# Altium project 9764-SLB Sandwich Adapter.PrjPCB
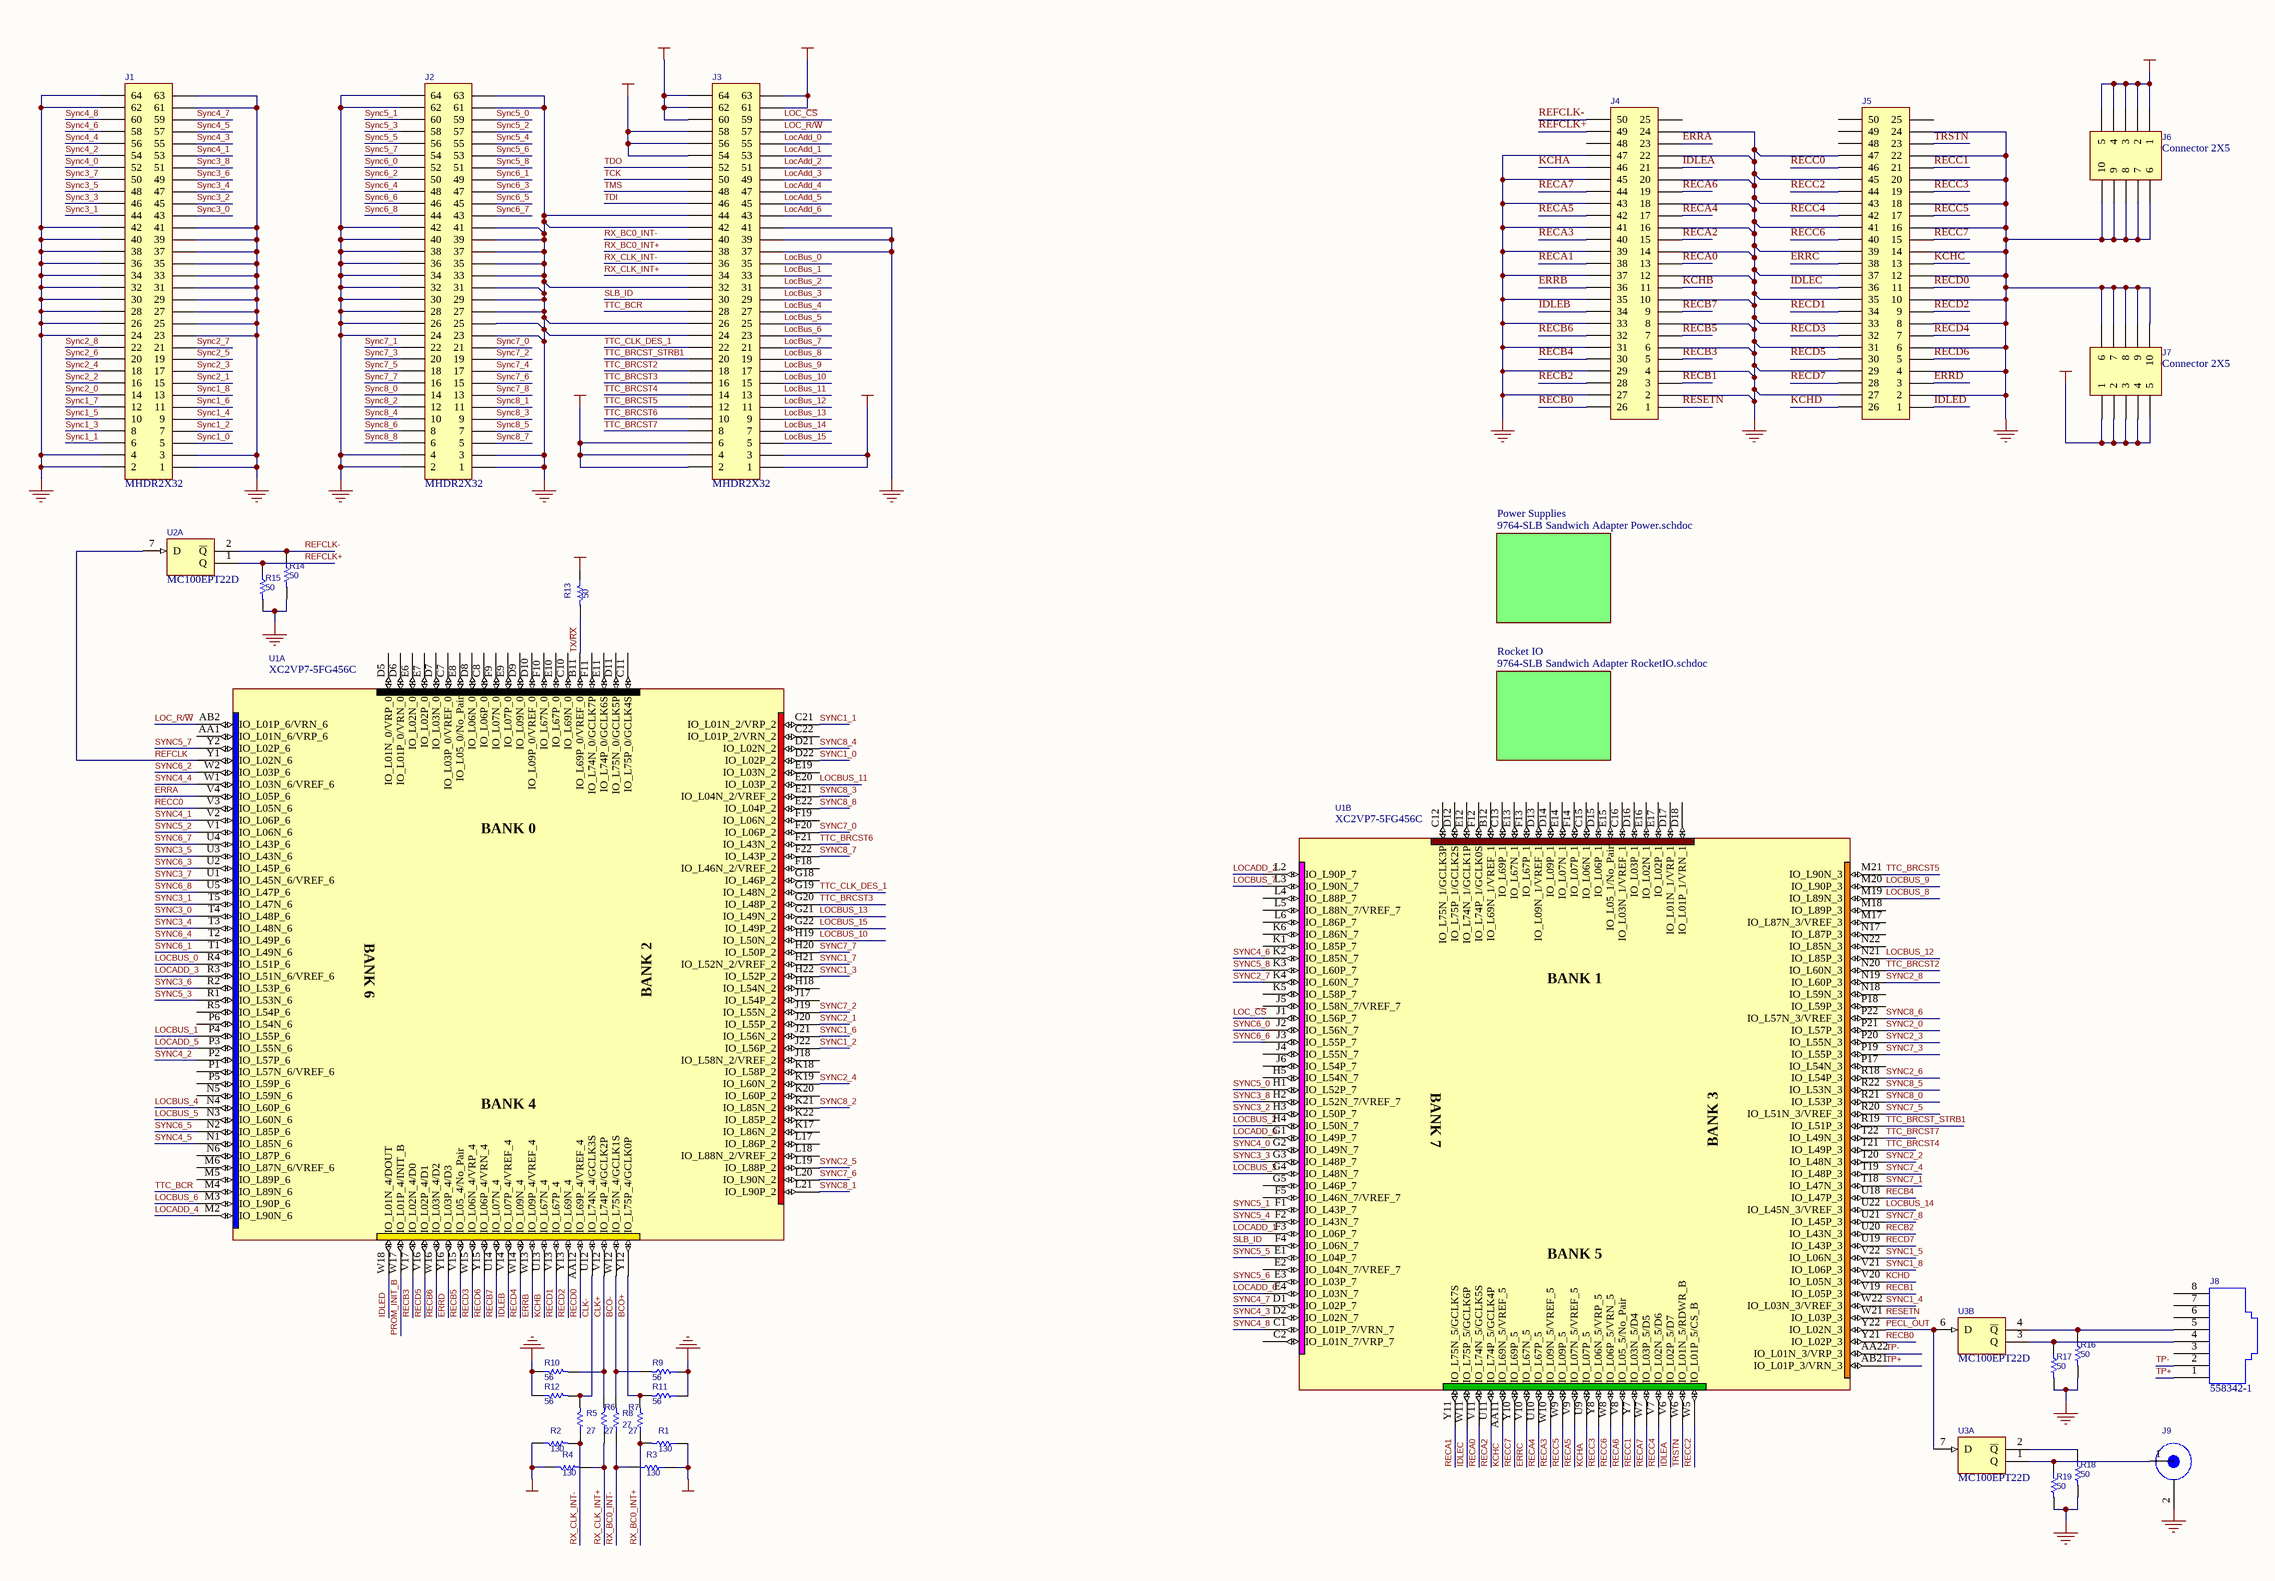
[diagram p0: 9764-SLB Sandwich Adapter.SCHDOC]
3 sheets, 137 parts. Net scope: global (net labels, ports and power ports of the same name join across sheets).
Board file: 9764-SLB Sandwich Adapter.PCBDOC
Sheets:
  9764-SLB Sandwich Adapter.SCHDOC
    Power Supplies = 9764-SLB Sandwich Adapter Power.SCHDOC
    Rocket IO = 9764-SLB Sandwich Adapter RocketIO.SCHDOC

## Sheet 9764-SLB Sandwich Adapter.SCHDOC
size C

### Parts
J1  MHDR2X32  [Molex-71436-0464]
J2  MHDR2X32  [Molex-71436-0464]
J3  MHDR2X32  [Molex-71436-0464]
J4  (no value)  [Samtec-TFM-150-XX-X-D]
J5  (no value)  [Samtec-TFM-150-XX-X-D]
J6  Connector 2X5  [Samtec-TFM-110-XX-X-D]
J7  Connector 2X5  [Samtec-TFM-110-XX-X-D]
J8  558342-1  [558342-1]
J9  COAX  [Johnson-SMA]  (value not drawn)
R1  130  [CR1608-0603]
R2  130  [CR1608-0603]
R3  130  [CR1608-0603]
R4  130  [CR1608-0603]
R5  27  [CR1608-0603]
R6  27  [CR1608-0603]
R7  27  [CR1608-0603]
R8  27  [CR1608-0603]
R9  56  [CR1608-0603]
R10  56  [CR1608-0603]
R11  56  [CR1608-0603]
R12  56  [CR1608-0603]
R13  50  [CR1608-0603]
R14  50  [CR1608-0603]
R15  50  [CR1608-0603]
R16  50  [CR1608-0603]
R17  50  [CR1608-0603]
R18  50  [CR1608-0603]
R19  50  [CR1608-0603]
U1  XC2VP7-5FG456C  [FG456]  (parts A,B of 5)
U2  MC100EPT22D  [751-06]  (part A of 2)
U3  MC100EPT22D  [751-06]  (parts A,B of 2)

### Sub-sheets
Power Supplies = 9764-SLB Sandwich Adapter Power.schdoc: no entries
Rocket IO = 9764-SLB Sandwich Adapter RocketIO.schdoc: no entries

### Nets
+2.5V: J3.54 J3.56 J3.58 R13.1
+3.3V: J3.1 J3.2 J3.3 J3.4 J3.6 J3.60 J3.61 J3.62 J3.63 J3.64 J6.1 J6.2 J6.3 J6.4 J6.5 J7.1 J7.2 J7.3 J7.4 J7.5 R1.1 R2.1 R3.1 R4.1 U2.8(VCC) U3.8(VCC)
GND: J1.1 J1.2 J1.3 J1.4 J1.23 J1.24 J1.25 J1.26 J1.27 J1.28 J1.29 J1.30 J1.31 J1.32 J1.33 J1.34 J1.35 J1.36 J1.37 J1.38 J1.39 J1.40 J1.41 J1.42 J1.61 J1.62 J1.63 J1.64 J2.1 J2.2 J2.3 J2.4 J2.23 J2.24 J2.25 J2.26 J2.27 J2.28 J2.29 J2.30 J2.31 J2.32 J2.33 J2.34 J2.35 J2.36 J2.37 J2.38 J2.39 J2.40 J2.41 J2.42 J2.61 J2.62 J2.63 J2.64 J3.24 J3.26 J3.32 J3.37 J3.39 J3.41 J3.42 J3.44 J4.2 J4.4 J4.6 J4.8 J4.10 J4.12 J4.14 J4.16 J4.18 J4.20 J4.22 J4.24 J4.27 J4.29 J4.31 J4.33 J4.35 J4.37 J4.39 J4.41 J4.43 J4.45 J4.47 J5.2 J5.4 J5.6 J5.8 J5.10 J5.12 J5.14 J5.16 J5.18 J5.20 J5.22 J5.24 J5.27 J5.29 J5.31 J5.33 J5.35 J5.37 J5.39 J5.41 J5.43 J5.45 J5.47 J6.6 J6.7 J6.8 J6.9 J6.10 J7.6 J7.7 J7.8 J7.9 J7.10 J9.2 R9.1 R10.1 R11.1 R12.1 R14.2 R15.2 R16.2 R17.2 R18.2 R19.2 U2.5(GND) U3.5(GND)
BCO+: R7.2 R11.2 U1.Y12(IO_L75P_4/GCLK0P)
BCO-: R6.2 R9.2 U1.W12(IO_L75N_4/GCLK1S)
CLK+: R8.2 R10.2 U1.V12(IO_L74P_4/GCLK2P)
CLK-: R5.2 R12.2 U1.U12(IO_L74N_4/GCLK3S)
ERRA: J4.23 U1.V4(IO_L05P_6)
ERRB: J4.36 U1.W13(IO_L09P_4/VREF_4)
ERRC: J5.38 U1.V10(IO_L67N_5)
ERRD: J5.3 U1.Y16(IO_L03P_4/D3)
IDLEA: J4.21 U1.V6(IO_L02P_5/D7)
IDLEB: J4.34 U1.V14(IO_L07P_4/VREF_4)
IDLEC: J5.36 U1.W11(IO_L75P_5/GCLK6P)
IDLED: J5.1 U1.W18(IO_L01N_4/DOUT)
KCHA: J4.46 U1.U9(IO_L07P_5)
KCHB: J4.11 U1.U13(IO_L67N_4)
KCHC: J5.13 U1.AA11(IO_L69N_5/VREF_5)
KCHD: J5.26 U1.V20(IO_L05N_3)
LOC_~{CS}: J3.59 U1.J1(IO_L56P_7)
LOC_R/~{W}: J3.57 U1.AB2(IO_L01P_6/VRN_6)
LocAdd_0: J3.55 U1.G1(IO_L49P_7)
LocAdd_1: J3.53 U1.F3(IO_L06P_7)
LocAdd_2: J3.51 U1.L2(IO_L90P_7)
LocAdd_3: J3.49 U1.R3(IO_L51N_6/VREF_6)
LocAdd_4: J3.47 U1.M2(IO_L90N_6)
LocAdd_5: J3.45 U1.P3(IO_L55N_6)
LocAdd_6: J3.43 U1.E4(IO_L03N_7)
LocBus_0: J3.35 U1.R4(IO_L51P_6)
LocBus_1: J3.33 U1.P4(IO_L55P_6)
LocBus_2: J3.31 U1.H4(IO_L50N_7)
LocBus_3: J3.29 U1.G4(IO_L48N_7)
LocBus_4: J3.27 U1.N4(IO_L60P_6)
LocBus_5: J3.25 U1.N3(IO_L60N_6)
LocBus_6: J3.23 U1.M3(IO_L90P_6)
LocBus_7: J3.21 U1.L3(IO_L90N_7)
LocBus_8: J3.19 U1.M19(IO_L89N_3)
LocBus_9: J3.17 U1.M20(IO_L90P_3)
LocBus_10: J3.15 U1.H19(IO_L50N_2)
LocBus_11: J3.13 U1.E20(IO_L03P_2)
LocBus_12: J3.11 U1.N21(IO_L85P_3)
LocBus_13: J3.9 U1.G21(IO_L49N_2)
LocBus_14: J3.7 U1.U22(IO_L45N_3/VREF_3)
LocBus_15: J3.5 U1.G22(IO_L49P_2)
PECL_OUT: U1.Y22(IO_L02N_3) U3.6(D) U3.7(D)
PROM_INIT_B: U1.W17(IO_L01P_4/INIT_B)
RECA0: J4.13 U1.V11(IO_L74N_5/GCLK5S)
RECA1: J4.38 U1.Y11(IO_L75N_5/GCLK7S)
RECA2: J4.15 U1.U11(IO_L74P_5/GCLK4P)
RECA3: J4.40 U1.W10(IO_L09N_5/VREF_5)
RECA4: J4.17 U1.U10(IO_L67P_5)
RECA5: J4.42 U1.V9(IO_L07N_5/VREF_5)
RECA6: J4.19 U1.V8(IO_L05_5/No_Pair)
RECA7: J4.44 U1.W7(IO_L03P_5/D5)
RECB0: J4.26 U1.Y21(IO_L02P_3)
RECB1: J4.3 U1.V19(IO_L05P_3)
RECB2: J4.28 U1.U20(IO_L43N_3)
RECB3: J4.5 U1.V17(IO_L02N_4/D0)
RECB4: J4.30 U1.U18(IO_L47P_3)
RECB5: J4.7 U1.V15(IO_L05_4/No_Pair)
RECB6: J4.32 U1.W16(IO_L03N_4/D2)
RECB7: J4.9 U1.U14(IO_L07N_4)
RECC0: J5.46 U1.V3(IO_L05N_6)
RECC1: J5.21 U1.Y7(IO_L03N_5/D4)
RECC2: J5.44 U1.W5(IO_L01P_5/CS_B)
RECC3: J5.19 U1.Y8(IO_L06N_5/VRP_5)
RECC4: J5.42 U1.V7(IO_L02N_5/D6)
RECC5: J5.17 U1.W9(IO_L09P_5)
RECC6: J5.40 U1.W8(IO_L06P_5/VRN_5)
RECC7: J5.15 U1.Y10(IO_L69P_5)
RECD0: J5.11 U1.AA12(IO_L69P_4/VREF_4)
RECD1: J5.34 U1.V13(IO_L67P_4)
RECD2: J5.9 U1.Y13(IO_L69N_4)
RECD3: J5.32 U1.W15(IO_L06N_4/VRP_4)
RECD4: J5.7 U1.W14(IO_L09N_4)
RECD5: J5.30 U1.V16(IO_L02P_4/D1)
RECD6: J5.5 U1.Y15(IO_L06P_4/VRN_4)
RECD7: J5.28 U1.U19(IO_L43P_3)
REFCLK: U1.Y1(IO_L02N_6) U2.7(D)
REFCLK+: J4.49 R15.1 U2.1(Q)
REFCLK-: J4.50 R14.1 U2.2(~{Q})
RESETN: J4.1 U1.W21(IO_L03P_3)
RX_BC0_INT+: J3.38 R1.2 R7.1
RX_BC0_INT-: J3.40 R3.2 R6.1
RX_CLK_INT+: J3.34 R4.2 R8.1
RX_CLK_INT-: J3.36 R2.2 R5.1
SLB_ID: J3.30 U1.F4(IO_L06N_7)
Sync1_0: J1.5 U1.D22(IO_L02P_2)
Sync1_1: J1.6 U1.C21(IO_L01N_2/VRP_2)
Sync1_2: J1.7 U1.J22(IO_L56P_2)
Sync1_3: J1.8 U1.H22(IO_L52P_2)
Sync1_4: J1.9 U1.W22(IO_L03N_3/VREF_3)
Sync1_5: J1.10 U1.V22(IO_L06N_3)
Sync1_6: J1.11 U1.J21(IO_L56N_2)
Sync1_7: J1.12 U1.H21(IO_L52N_2/VREF_2)
Sync1_8: J1.13 U1.V21(IO_L06P_3)
Sync2_0: J1.14 U1.P21(IO_L57P_3)
Sync2_1: J1.15 U1.J20(IO_L55P_2)
Sync2_2: J1.16 U1.T20(IO_L48N_3)
Sync2_3: J1.17 U1.P20(IO_L55N_3)
Sync2_4: J1.18 U1.K19(IO_L60N_2)
Sync2_5: J1.19 U1.L19(IO_L88P_2)
Sync2_6: J1.20 U1.R18(IO_L54P_3)
Sync2_7: J1.21 U1.K4(IO_L60N_7)
Sync2_8: J1.22 U1.N19(IO_L60P_3)
Sync3_0: J1.43 U1.T4(IO_L48P_6)
Sync3_1: J1.44 U1.T5(IO_L47N_6)
Sync3_2: J1.45 U1.H3(IO_L50P_7)
Sync3_3: J1.46 U1.G3(IO_L48P_7)
Sync3_4: J1.47 U1.T3(IO_L48N_6)
Sync3_5: J1.48 U1.U3(IO_L43N_6)
Sync3_6: J1.49 U1.R2(IO_L53P_6)
Sync3_7: J1.50 U1.U1(IO_L45N_6/VREF_6)
Sync3_8: J1.51 U1.H2(IO_L52N_7/VREF_7)
Sync4_0: J1.52 U1.G2(IO_L49N_7)
Sync4_1: J1.53 U1.V2(IO_L06P_6)
Sync4_2: J1.54 U1.P2(IO_L57P_6)
Sync4_3: J1.55 U1.D2(IO_L02N_7)
Sync4_4: J1.56 U1.W1(IO_L03N_6/VREF_6)
Sync4_5: J1.57 U1.N1(IO_L85N_6)
Sync4_6: J1.58 U1.K2(IO_L85N_7)
Sync4_7: J1.59 U1.D1(IO_L02P_7)
Sync4_8: J1.60 U1.C1(IO_L01P_7/VRN_7)
Sync5_0: J2.59 U1.H1(IO_L52P_7)
Sync5_1: J2.60 U1.F1(IO_L43P_7)
Sync5_2: J2.57 U1.V1(IO_L06N_6)
Sync5_3: J2.58 U1.R1(IO_L53N_6)
Sync5_4: J2.55 U1.F2(IO_L43N_7)
Sync5_5: J2.56 U1.E1(IO_L04P_7)
Sync5_6: J2.53 U1.E3(IO_L03P_7)
Sync5_7: J2.54 U1.Y2(IO_L02P_6)
Sync5_8: J2.51 U1.K3(IO_L60P_7)
Sync6_0: J2.52 U1.J2(IO_L56N_7)
Sync6_1: J2.49 U1.T1(IO_L49N_6)
Sync6_2: J2.50 U1.W2(IO_L03P_6)
Sync6_3: J2.47 U1.U2(IO_L45P_6)
Sync6_4: J2.48 U1.T2(IO_L49P_6)
Sync6_5: J2.45 U1.N2(IO_L85P_6)
Sync6_6: J2.46 U1.J3(IO_L55P_7)
Sync6_7: J2.43 U1.U4(IO_L43P_6)
Sync6_8: J2.44 U1.U5(IO_L47P_6)
Sync7_0: J2.21 U1.F20(IO_L06P_2)
Sync7_1: J2.22 U1.T18(IO_L47N_3)
Sync7_2: J2.19 U1.J19(IO_L55N_2)
Sync7_3: J2.20 U1.P19(IO_L55P_3)
Sync7_4: J2.17 U1.T19(IO_L48P_3)
Sync7_5: J2.18 U1.R20(IO_L51N_3/VREF_3)
Sync7_6: J2.15 U1.L20(IO_L90N_2)
Sync7_7: J2.16 U1.H20(IO_L50P_2)
Sync7_8: J2.13 U1.U21(IO_L45P_3)
Sync8_0: J2.14 U1.R21(IO_L53P_3)
Sync8_1: J2.11 U1.L21(IO_L90P_2)
Sync8_2: J2.12 U1.K21(IO_L85N_2)
Sync8_3: J2.9 U1.E21(IO_L04N_2/VREF_2)
Sync8_4: J2.10 U1.D21(IO_L02N_2)
Sync8_5: J2.7 U1.R22(IO_L53N_3)
Sync8_6: J2.8 U1.P22(IO_L57N_3/VREF_3)
Sync8_7: J2.5 U1.F22(IO_L43P_2)
Sync8_8: J2.6 U1.E22(IO_L04P_2)
TCK: J3.50
TDI: J3.46
TDO: J3.52
TMS: J3.48
TP+: J8.1 U1.AB21(IO_L01P_3/VRN_3)
TP-: J8.2 U1.AA22(IO_L01N_3/VRP_3)
TRSTN: J5.23 U1.W6(IO_L01N_5/RDWR_B)
TTC_BCR: J3.28 U1.M4(IO_L89N_6)
TTC_BRCST2: J3.18 U1.N20(IO_L60N_3)
TTC_BRCST3: J3.16 U1.G20(IO_L48P_2)
TTC_BRCST4: J3.14 U1.T21(IO_L49P_3)
TTC_BRCST5: J3.12 U1.M21(IO_L90N_3)
TTC_BRCST6: J3.10 U1.F21(IO_L43N_2)
TTC_BRCST7: J3.8 U1.T22(IO_L49N_3)
TTC_BRCST_STRB1: J3.20 U1.R19(IO_L51P_3)
TTC_CLK_DES_1: J3.22 U1.G19(IO_L48N_2)
TX/~{RX}: R13.2 U1.B11(IO_L69P_0/VREF_0)
NetJ8_4: J8.4 R17.1 U3.3(Q)
NetJ8_5: J8.5 R16.1 U3.4(~{Q})
NetJ9_1: J9.1 R19.1 U3.1(Q)
NetR18_1: R18.1 U3.2(~{Q})

Not connected (* = marked no-connect by the designer): J4 25 48; J5 25 48 49 50; J8 3 6 7 8; U1 AA1(IO_L01N_6/VRP_6) B12(IO_L69N_1/VREF_1) C2(IO_L01N_7/VRP_7) C7(IO_L03P_0/VREF_0) C8(IO_L06P_0) C10(IO_L69N_0) C11(IO_L75P_0/GCLK4S) C12(IO_L75N_1/GCLK3P) C13(IO_L69P_1) C15(IO_L06N_1) C16(IO_L03N_1/VREF_1) C22(IO_L01P_2/VRN_2) D5(IO_L01N_0/VRP_0) D6(IO_L01P_0/VRN_0) D7(IO_L03N_0) D8(IO_L06N_0) D9(IO_L09N_0) D10(IO_L09P_0/VREF_0) D11(IO_L75N_0/GCLK5P) D12(IO_L75P_1/GCLK2S) D13(IO_L09N_1/VREF_1) D14(IO_L09P_1) D15(IO_L06P_1) D16(IO_L03P_1) D17(IO_L01N_1/VRP_1) D18(IO_L01P_1/VRN_1) E2(IO_L04N_7/VREF_7) E6(IO_L02N_0) E7(IO_L02P_0) E8(IO_L05_0/No_Pair) E9(IO_L07P_0) E10(IO_L67P_0) E11(IO_L74P_0/GCLK6S) E12(IO_L74N_1/GCLK1P) E13(IO_L67N_1) E14(IO_L07N_1) E15(IO_L05_1/No_Pair) E16(IO_L02N_1) E17(IO_L02P_1) E19(IO_L03N_2) F5(IO_L46N_7/VREF_7) F9(IO_L07N_0) F10(IO_L67N_0) F11(IO_L74N_0/GCLK7P) F12(IO_L74P_1/GCLK0S) F13(IO_L67P_1) F14(IO_L07P_1) F18(IO_L46N_2/VREF_2) F19(IO_L06N_2) G5(IO_L46P_7) G18(IO_L46P_2) H5(IO_L54N_7) H18(IO_L54N_2) J4(IO_L55N_7) J5(IO_L58N_7/VREF_7) J6(IO_L54P_7) J17(IO_L54P_2) J18(IO_L58N_2/VREF_2) K1(IO_L85P_7) K5(IO_L58P_7) K6(IO_L86N_7) K17(IO_L86N_2) K18(IO_L58P_2) K20(IO_L60P_2) K22(IO_L85P_2) L4(IO_L88P_7) L5(IO_L88N_7/VREF_7) L6(IO_L86P_7) L17(IO_L86P_2) L18(IO_L88N_2/VREF_2) M5(IO_L89P_6) M6(IO_L87N_6/VREF_6) M17(IO_L87N_3/VREF_3) M18(IO_L89P_3) N5(IO_L59N_6) N6(IO_L87P_6) N17(IO_L87P_3) N18(IO_L59N_3) N22(IO_L85N_3) P1(IO_L57N_6/VREF_6) P5(IO_L59P_6) P6(IO_L54N_6) P17(IO_L54N_3) P18(IO_L59P_3) R5(IO_L54P_6)

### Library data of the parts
J1-J3 = MHDR2X32: Header, 32-Pin, Dual row
J4 J5 = Connector 2X25: Connector, 25-Pin, Dual row
J6 J7 = Connector 2X5: Connector, 5-Pin, Dual row; Manufacturer: Generic Components
J8 = 558342-1: AMP RJ45 8 Pin CAT5
R1-R19 = Resistor: Manufacturer: Generic Components; Class I: Passive
U1 = XC2VP7-5FG456C: Virtex-II Pro Platform FPGA, 456-Ball FBGA, Speed Grade 5, 248 User I/Os, Commercial Grade; Manufacturer Recommendation: Solder pad diameter 0.45mm SMD; Package Information: Latest Revision: ver1.1, Apr-2001; User I/Os: 248 Available; Code - JEDEC: MO-151-AAJ-1
U2 U3 = MC100EPT22D: Dual LVTTL/LVCMOS to Differential LVPECL Translator; Package Information: Latest Revision: Sep-1999; Code - JEDEC: MS-012-AA; Code - IPC: SO8

## Sheet 9764-SLB Sandwich Adapter Power.SCHDOC
size C
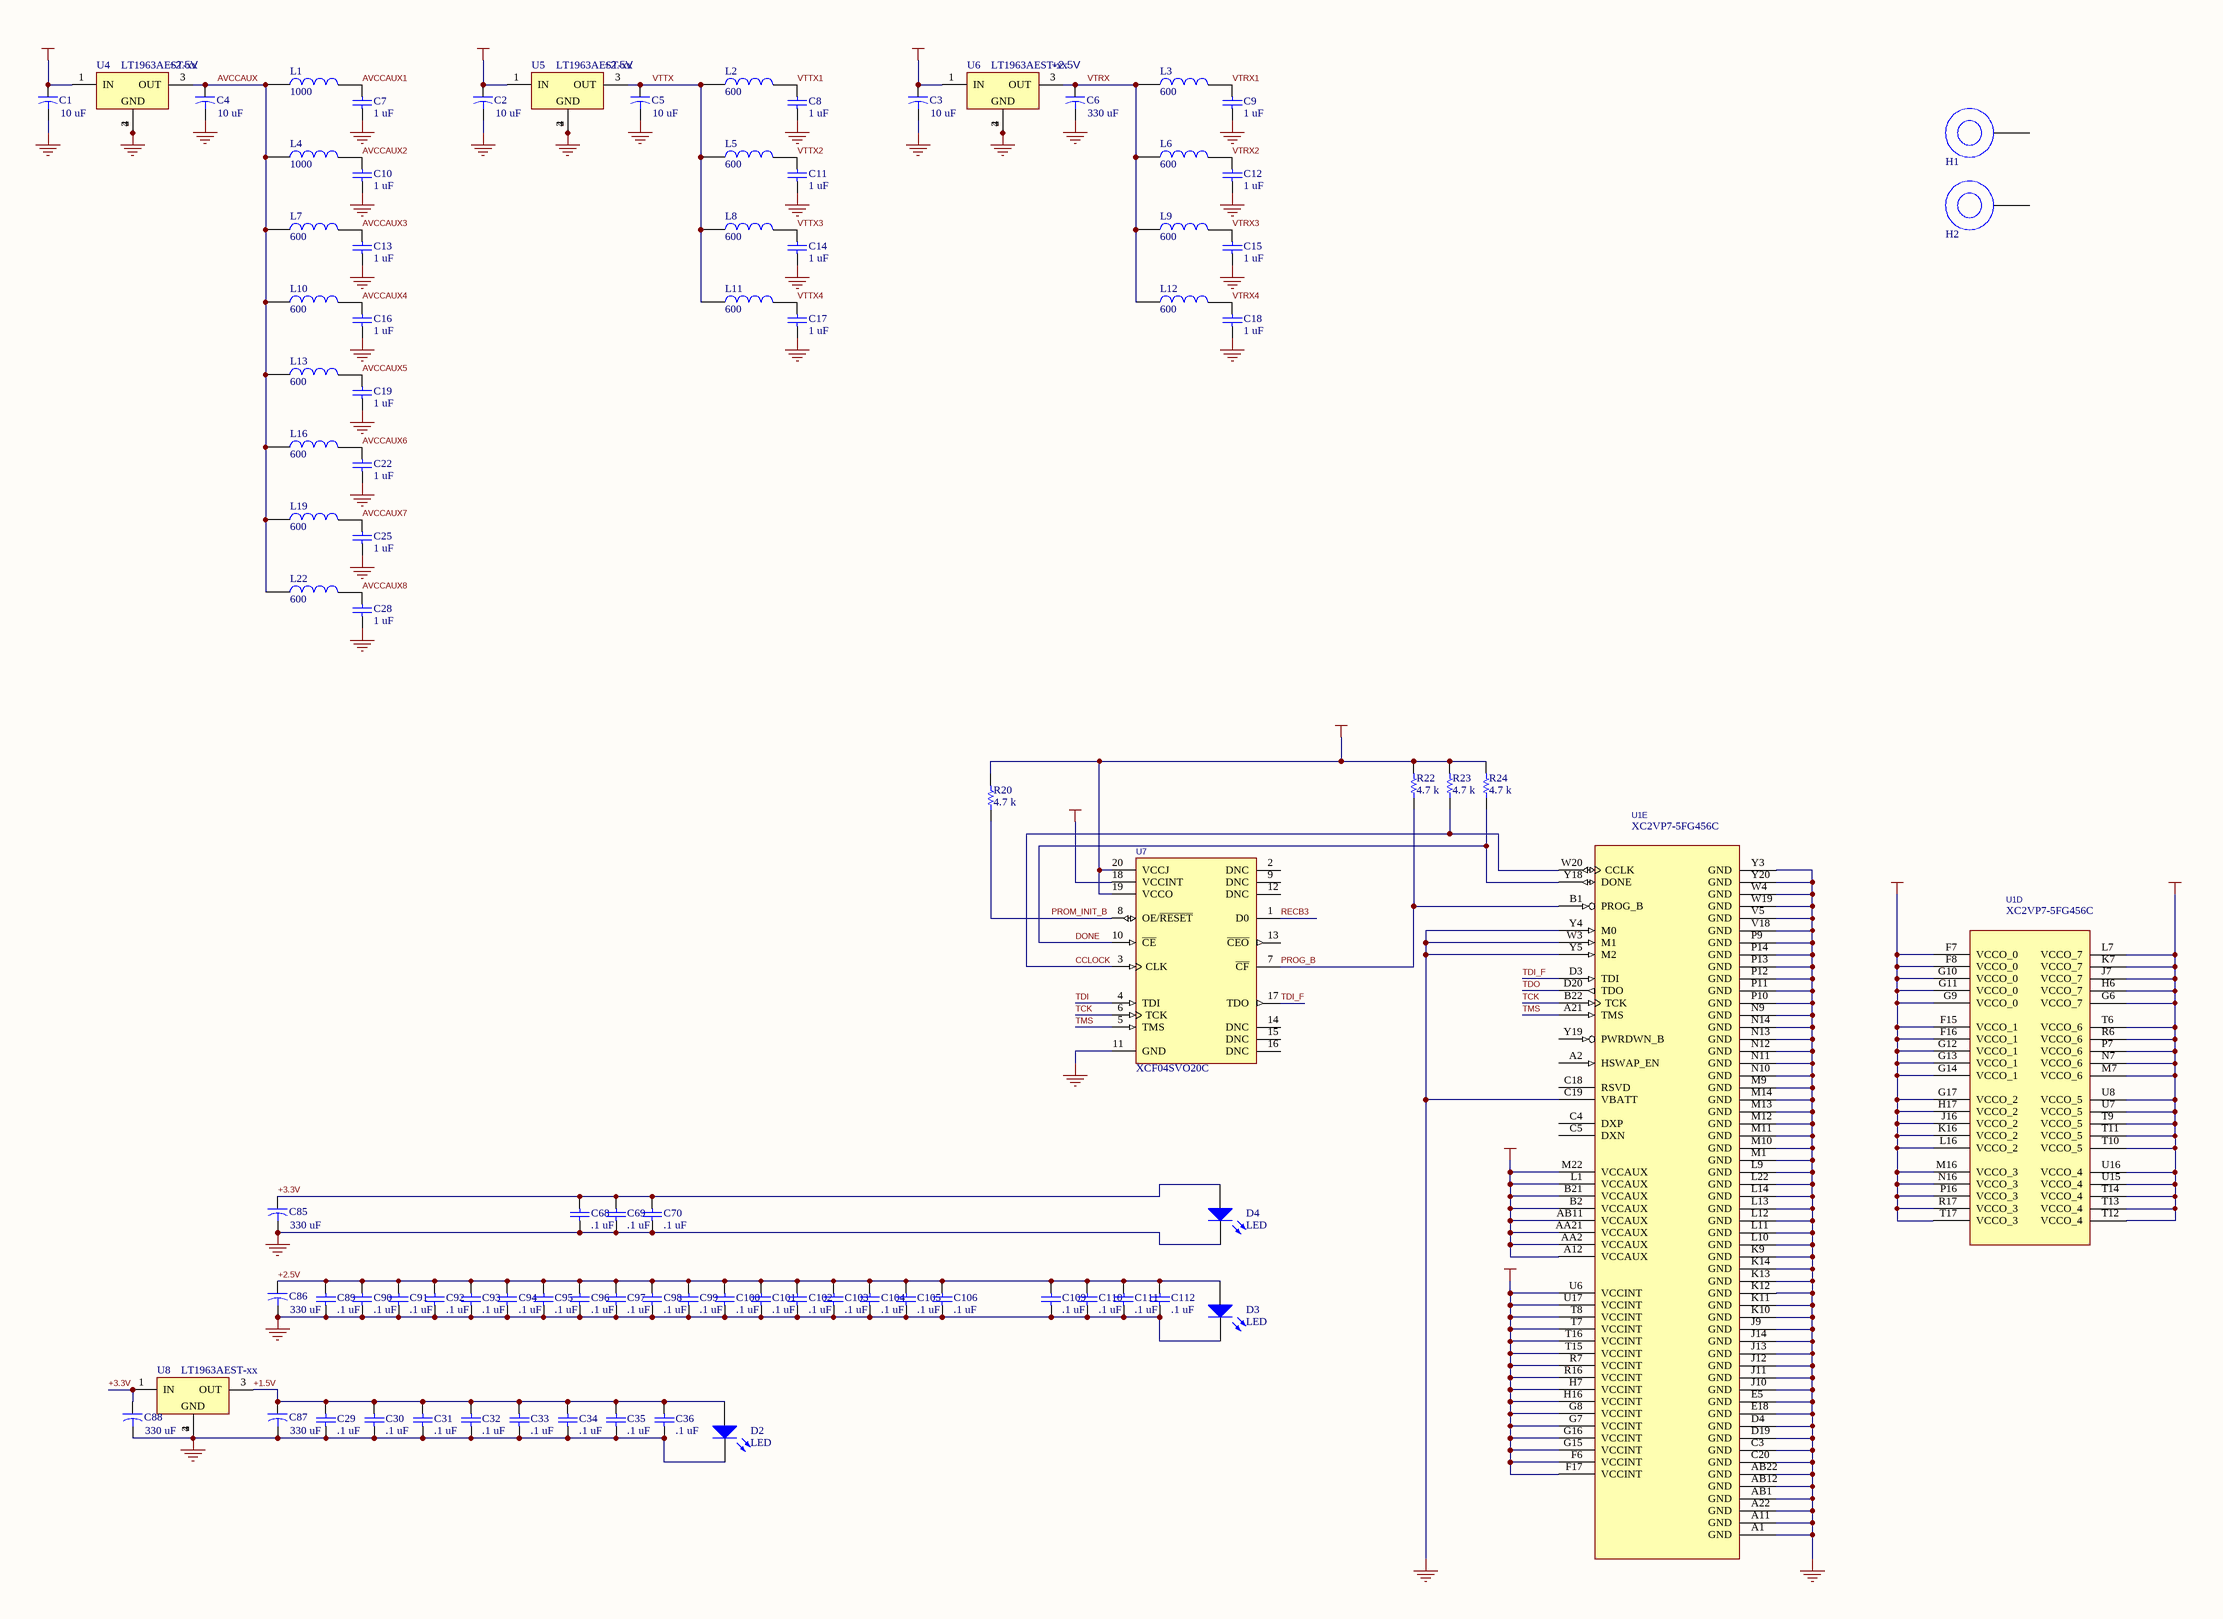
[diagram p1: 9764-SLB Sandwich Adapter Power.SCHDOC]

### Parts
C1  10 uF  [CT3528-1411]
C2  10 uF  [CT3528-1411]
C3  10 uF  [CT3528-1411]
C4  10 uF  [CT3528-1411]
C5  10 uF  [CT3528-1411]
C6  330 uF  [CT3528-1411]
C7  1 uF  [CC1005-0402]
C8  1 uF  [CC1005-0402]
C9  1 uF  [CC1005-0402]
C10  1 uF  [CC1005-0402]
C11  1 uF  [CC1005-0402]
C12  1 uF  [CC1005-0402]
C13  1 uF  [CC1005-0402]
C14  1 uF  [CC1005-0402]
C15  1 uF  [CC1005-0402]
C16  1 uF  [CC1005-0402]
C17  1 uF  [CC1005-0402]
C18  1 uF  [CC1005-0402]
C19  1 uF  [CC1005-0402]
C22  1 uF  [CC1005-0402]
C25  1 uF  [CC1005-0402]
C28  1 uF  [CC1005-0402]
C29  .1 uF  [CC1005-0402]
C30  .1 uF  [CC1005-0402]
C31  .1 uF  [CC1005-0402]
C32  .1 uF  [CC1005-0402]
C33  .1 uF  [CC1005-0402]
C34  .1 uF  [CC1005-0402]
C35  .1 uF  [CC1005-0402]
C36  .1 uF  [CC1005-0402]
C68  .1 uF  [CC1005-0402]
C69  .1 uF  [CC1005-0402]
C70  .1 uF  [CC1005-0402]
C85  330 uF  [CT3528-1411]
C86  330 uF  [CT3528-1411]
C87  330 uF  [CT3528-1411]
C88  330 uF  [CT3528-1411]
C89  .1 uF  [CC1005-0402]
C90  .1 uF  [CC1005-0402]
C91  .1 uF  [CC1005-0402]
C92  .1 uF  [CC1005-0402]
C93  .1 uF  [CC1005-0402]
C94  .1 uF  [CC1005-0402]
C95  .1 uF  [CC1005-0402]
C96  .1 uF  [CC1005-0402]
C97  .1 uF  [CC1005-0402]
C98  .1 uF  [CC1005-0402]
C99  .1 uF  [CC1005-0402]
C100  .1 uF  [CC1005-0402]
C101  .1 uF  [CC1005-0402]
C102  .1 uF  [CC1005-0402]
C103  .1 uF  [CC1005-0402]
C104  .1 uF  [CC1005-0402]
C105  .1 uF  [CC1005-0402]
C106  .1 uF  [CC1005-0402]
C109  .1 uF  [CC1005-0402]
C110  .1 uF  [CC1005-0402]
C111  .1 uF  [CC1005-0402]
C112  .1 uF  [CC1005-0402]
D2  LED  [HSMx-C150 LED]
D3  LED  [HSMx-C150 LED]
D4  LED  [HSMx-C150 LED]
H1  MH  [Mounting Hole]  (value not drawn)
H2  MH  [Mounting Hole]  (value not drawn)
L1  1000  [CR1608-0603]
L2  600  [CR1608-0603]
L3  600  [CR1608-0603]
L4  1000  [CR1608-0603]
L5  600  [CR1608-0603]
L6  600  [CR1608-0603]
L7  600  [CR1608-0603]
L8  600  [CR1608-0603]
L9  600  [CR1608-0603]
L10  600  [CR1608-0603]
L11  600  [CR1608-0603]
L12  600  [CR1608-0603]
L13  600  [CR1608-0603]
L16  600  [CR1608-0603]
L19  600  [CR1608-0603]
L22  600  [CR1608-0603]
R20  4.7 k  [CR1608-0603]
R22  4.7 k  [CR1608-0603]
R23  4.7 k  [CR1608-0603]
R24  4.7 k  [CR1608-0603]
U1  XC2VP7-5FG456C  [FG456]  (parts D,E of 5)
U4  LT1963AEST-xx  [SOT-223]
U5  LT1963AEST-xx  [SOT-223]
U6  LT1963AEST-xx  [SOT-223]
U7  XCF04SVO20C  [VO20]
U8  LT1963AEST-xx  [SOT-223]

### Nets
+1.5V: C29.1 C30.1 C31.1 C32.1 C33.1 C34.1 C35.1 C36.1 C87.1 D2.1(A) U1.F6(VCCINT) U1.F17(VCCINT) U1.G7(VCCINT) U1.G8(VCCINT) U1.G15(VCCINT) U1.G16(VCCINT) U1.H7(VCCINT) U1.H16(VCCINT) U1.R7(VCCINT) U1.R16(VCCINT) U1.T7(VCCINT) U1.T8(VCCINT) U1.T15(VCCINT) U1.T16(VCCINT) U1.U6(VCCINT) U1.U17(VCCINT) U8.3(OUT)
+2.5V: C86.1 C89.1 C90.1 C91.1 C92.1 C93.1 C94.1 C95.1 C96.1 C97.1 C98.1 C99.1 C100.1 C101.1 C102.1 C103.1 C104.1 C105.1 C106.1 C109.1 C110.1 C111.1 C112.1 D3.1(A) R20.2 R22.2 R23.2 R24.2 U1.A12(VCCAUX) U1.AA2(VCCAUX) U1.AA21(VCCAUX) U1.AB11(VCCAUX) U1.B2(VCCAUX) U1.B21(VCCAUX) U1.F7(VCCO_0) U1.F8(VCCO_0) U1.F15(VCCO_1) U1.F16(VCCO_1) U1.G6(VCCO_7) U1.G9(VCCO_0) U1.G10(VCCO_0) U1.G11(VCCO_0) U1.G12(VCCO_1) U1.G13(VCCO_1) U1.G14(VCCO_1) U1.G17(VCCO_2) U1.H6(VCCO_7) U1.H17(VCCO_2) U1.J7(VCCO_7) U1.J16(VCCO_2) U1.K7(VCCO_7) U1.K16(VCCO_2) U1.L1(VCCAUX) U1.L7(VCCO_7) U1.L16(VCCO_2) U1.M7(VCCO_6) U1.M16(VCCO_3) U1.M22(VCCAUX) U1.N7(VCCO_6) U1.N16(VCCO_3) U1.P7(VCCO_6) U1.P16(VCCO_3) U1.R6(VCCO_6) U1.R17(VCCO_3) U1.T6(VCCO_6) U1.T9(VCCO_5) U1.T10(VCCO_5) U1.T11(VCCO_5) U1.T12(VCCO_4) U1.T13(VCCO_4) U1.T14(VCCO_4) U1.T17(VCCO_3) U1.U7(VCCO_5) U1.U8(VCCO_5) U1.U15(VCCO_4) U1.U16(VCCO_4) U7.19(VCCO) U7.20(VCCJ)
+3.3V: C1.1 C2.1 C3.1 C68.1 C69.1 C70.1 C85.1 C88.1 D4.1(A) U4.1(IN) U5.1(IN) U6.1(IN) U7.18(VCCINT) U8.1(IN)
GND: C1.2 C2.2 C3.2 C4.2 C5.2 C6.2 C7.2 C8.2 C9.2 C10.2 C11.2 C12.2 C13.2 C14.2 C15.2 C16.2 C17.2 C18.2 C19.2 C22.2 C25.2 C28.2 C29.2 C30.2 C31.2 C32.2 C33.2 C34.2 C35.2 C36.2 C68.2 C69.2 C70.2 C85.2 C86.2 C87.2 C88.2 C89.2 C90.2 C91.2 C92.2 C93.2 C94.2 C95.2 C96.2 C97.2 C98.2 C99.2 C100.2 C101.2 C102.2 C103.2 C104.2 C105.2 C106.2 C109.2 C110.2 C111.2 C112.2 D2.2(K) D3.2(K) D4.2(K) U1.A1(GND) U1.A11(GND) U1.A22(GND) U1.AB1(GND) U1.AB12(GND) U1.AB22(GND) U1.C3(GND) U1.C19(VBATT) U1.C20(GND) U1.D4(GND) U1.D19(GND) U1.E5(GND) U1.E18(GND) U1.J9(GND) U1.J10(GND) U1.J11(GND) U1.J12(GND) U1.J13(GND) U1.J14(GND) U1.K9(GND) U1.K10(GND) U1.K11(GND) U1.K12(GND) U1.K13(GND) U1.K14(GND) U1.L9(GND) U1.L10(GND) U1.L11(GND) U1.L12(GND) U1.L13(GND) U1.L14(GND) U1.L22(GND) U1.M1(GND) U1.M9(GND) U1.M10(GND) U1.M11(GND) U1.M12(GND) U1.M13(GND) U1.M14(GND) U1.N9(GND) U1.N10(GND) U1.N11(GND) U1.N12(GND) U1.N13(GND) U1.N14(GND) U1.P9(GND) U1.P10(GND) U1.P11(GND) U1.P12(GND) U1.P13(GND) U1.P14(GND) U1.V5(GND) U1.V18(GND) U1.W3(M1) U1.W4(GND) U1.W19(GND) U1.Y3(GND) U1.Y4(M0) U1.Y5(M2) U1.Y20(GND) U4.2(GND) U4.4 U5.2(GND) U5.4 U6.2(GND) U6.4 U7.11(GND) U8.2(GND) U8.4
AVCCAUX: C4.1 L1.2 L4.2 L7.2 L10.2 L13.2 L16.2 L19.2 L22.2 U4.3(OUT)
AVCCAUX1: C7.1 L1.1
AVCCAUX2: C10.1 L4.1
AVCCAUX3: C13.1 L7.1
AVCCAUX4: C16.1 L10.1
AVCCAUX5: C19.1 L13.1
AVCCAUX6: C22.1 L16.1
AVCCAUX7: C25.1 L19.1
AVCCAUX8: C28.1 L22.1
CCLOCK: R23.1 U1.W20(CCLK) U7.3(CLK)
DONE: R24.1 U1.Y18(DONE) U7.10(~{CE})
PROG_B: R22.1 U1.B1(PROG_B) U7.7(~{CF})
PROM_INIT_B: R20.1 U7.8(OE/~{RESET})
RECB3: U7.1(D0)
TCK: U1.B22(TCK) U7.6(TCK)
TDI: U7.4(TDI)
TDI_F: U1.D3(TDI) U7.17(TDO)
TDO: U1.D20(TDO)
TMS: U1.A21(TMS) U7.5(TMS)
VTRX: C6.1 L3.2 L6.2 L9.2 L12.2 U6.3(OUT)
VTRX1: C9.1 L3.1
VTRX2: C12.1 L6.1
VTRX3: C15.1 L9.1
VTRX4: C18.1 L12.1
VTTX: C5.1 L2.2 L5.2 L8.2 L11.2 U5.3(OUT)
VTTX1: C8.1 L2.1
VTTX2: C11.1 L5.1
VTTX3: C14.1 L8.1
VTTX4: C17.1 L11.1

Not connected (* = marked no-connect by the designer): H1 1; H2 1; U1 A2(HSWAP_EN) C4(DXP) C5(DXN) C18(RSVD) Y19(PWRDWN_B); U7 2(DNC) 9(DNC) 12(DNC) 13(~{CEO}) 14(DNC) 15(DNC) 16(DNC)

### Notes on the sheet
- (near U4) +2.5V
- (near U5) +2.5V
- +2.5V

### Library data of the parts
C1-C6 C85-C88 = Cap2: Capacitor; Manufacturer: Generic Components; Class I: Passive
C7-C19 C22 C25 C28-C36 C68-C70 C89-C106 C109-C112 = Cap: Capacitor; Manufacturer: Generic Components; Class I: Passive
D2-D4 = LED: General LED; Manufacturer: Generic Components; Class I: Optoelectronic
H1 H2 = MH: Mounting Hole
L1-L13 L16 L19 L22 = Inductor: Manufacturer: Generic Components; Class I: Passive
R20 R22-R24 = Resistor: as R1 on sheet 9764-SLB Sandwich Adapter
U1 = XC2VP7-5FG456C: as U1 on sheet 9764-SLB Sandwich Adapter
U4-U6 U8 = LT1963AEST-xx: Three-Terminal LDO Positive Voltage Regulator; Package Information: Latest Revision: Nov-1999; Note: Pin 2 is electrically connected to Pin 4 (TAB)
U7 = XCF04SVO20C: XCF00S Series, Platform Flash In-System Programmable Configuration 3.3V PROM, 20-Pin TSOP, 4-Megabit, Commercial Grade; Package Information: Latest Revision: ver1.0, May-2003; Code - JEDEC: MO-153-AC

## Sheet 9764-SLB Sandwich Adapter RocketIO.SCHDOC
size B
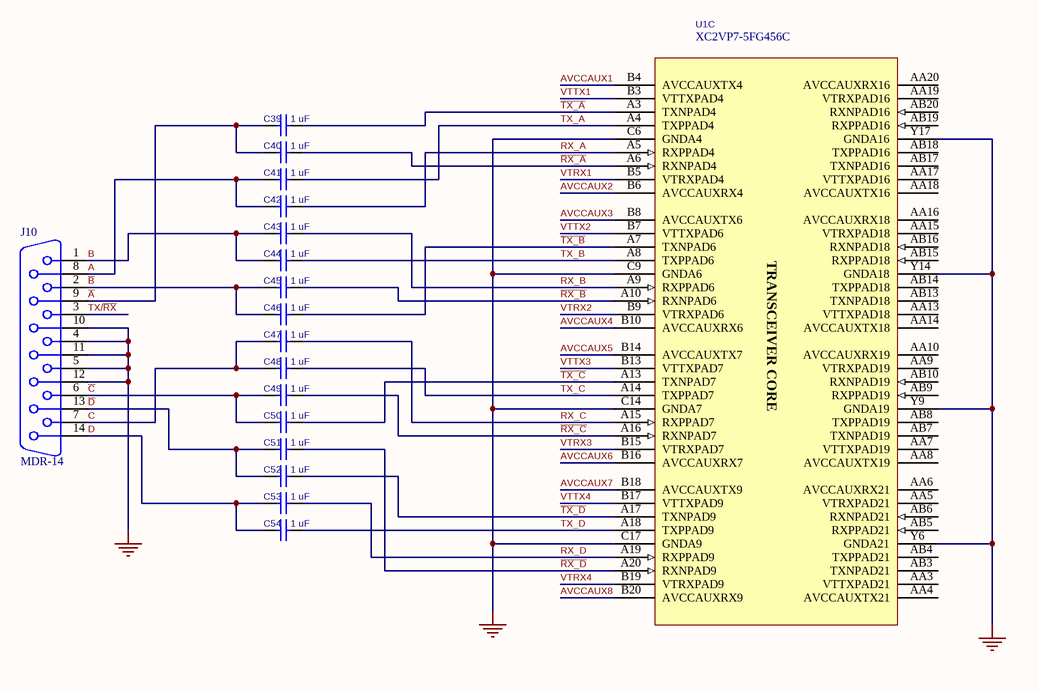
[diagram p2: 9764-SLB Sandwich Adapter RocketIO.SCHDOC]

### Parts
C39  1 uF  [CC1005-0402]
C40  1 uF  [CC1005-0402]
C41  1 uF  [CC1005-0402]
C42  1 uF  [CC1005-0402]
C43  1 uF  [CC1005-0402]
C44  1 uF  [CC1005-0402]
C45  1 uF  [CC1005-0402]
C46  1 uF  [CC1005-0402]
C47  1 uF  [CC1005-0402]
C48  1 uF  [CC1005-0402]
C49  1 uF  [CC1005-0402]
C50  1 uF  [CC1005-0402]
C51  1 uF  [CC1005-0402]
C52  1 uF  [CC1005-0402]
C53  1 uF  [CC1005-0402]
C54  1 uF  [CC1005-0402]
J10  MDR-14  [MDR-14]
U1  XC2VP7-5FG456C  [FG456]  (part C of 5)

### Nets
GND: J10.4 J10.5 J10.10 J10.11 J10.12 U1.C6(GNDA4) U1.C9(GNDA6) U1.C14(GNDA7) U1.C17(GNDA9) U1.Y6(GNDA21) U1.Y9(GNDA19) U1.Y14(GNDA18) U1.Y17(GNDA16)
~{A}: C39.1 C40.1 J10.9
~{B}: C45.1 C46.1 J10.2
~{C}: C49.1 C50.1 J10.6
~{D}: C51.1 C52.1 J10.13
~{RX_A}: C40.2 U1.A6(RXNPAD4)
~{RX_B}: C45.2 U1.A10(RXNPAD6)
~{RX_C}: C49.2 U1.A16(RXNPAD7)
~{RX_D}: C51.2 U1.A20(RXNPAD9)
~{TX_A}: C39.2 U1.A3(TXNPAD4)
~{TX_B}: C46.2 U1.A7(TXNPAD6)
~{TX_C}: C50.2 U1.A13(TXNPAD7)
~{TX_D}: C52.2 U1.A17(TXNPAD9)
A: C41.1 C42.1 J10.8
AVCCAUX1: U1.B4(AVCCAUXTX4)
AVCCAUX2: U1.B6(AVCCAUXRX4)
AVCCAUX3: U1.B8(AVCCAUXTX6)
AVCCAUX4: U1.B10(AVCCAUXRX6)
AVCCAUX5: U1.B14(AVCCAUXTX7)
AVCCAUX6: U1.B16(AVCCAUXRX7)
AVCCAUX7: U1.B18(AVCCAUXTX9)
AVCCAUX8: U1.B20(AVCCAUXRX9)
B: C43.1 C44.1 J10.1
C: C47.1 C48.1 J10.7
D: C53.1 C54.1 J10.14
RX_A: C42.2 U1.A5(RXPPAD4)
RX_B: C43.2 U1.A9(RXPPAD6)
RX_C: C47.2 U1.A15(RXPPAD7)
RX_D: C53.2 U1.A19(RXPPAD9)
TX/~{RX}: J10.3
TX_A: C41.2 U1.A4(TXPPAD4)
TX_B: C44.2 U1.A8(TXPPAD6)
TX_C: C48.2 U1.A14(TXPPAD7)
TX_D: C54.2 U1.A18(TXPPAD9)
VTRX1: U1.B5(VTRXPAD4)
VTRX2: U1.B9(VTRXPAD6)
VTRX3: U1.B15(VTRXPAD7)
VTRX4: U1.B19(VTRXPAD9)
VTTX1: U1.B3(VTTXPAD4)
VTTX2: U1.B7(VTTXPAD6)
VTTX3: U1.B13(VTTXPAD7)
VTTX4: U1.B17(VTTXPAD9)

Not connected (* = marked no-connect by the designer): U1 AA3(VTTXPAD21) AA4(AVCCAUXTX21) AA5(VTRXPAD21) AA6(AVCCAUXRX21) AA7(VTTXPAD19) AA8(AVCCAUXTX19) AA9(VTRXPAD19) AA10(AVCCAUXRX19) AA13(VTTXPAD18) AA14(AVCCAUXTX18) AA15(VTRXPAD18) AA16(AVCCAUXRX18) AA17(VTTXPAD16) AA18(AVCCAUXTX16) AA19(VTRXPAD16) AA20(AVCCAUXRX16) AB3(TXNPAD21) AB4(TXPPAD21) AB5(RXPPAD21) AB6(RXNPAD21) AB7(TXNPAD19) AB8(TXPPAD19) AB9(RXPPAD19) AB10(RXNPAD19) AB13(TXNPAD18) AB14(TXPPAD18) AB15(RXPPAD18) AB16(RXNPAD18) AB17(TXNPAD16) AB18(TXPPAD16) AB19(RXPPAD16) AB20(RXNPAD16)

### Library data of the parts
C39-C54 = Cap: as C7 on sheet 9764-SLB Sandwich Adapter Power
J10 = MDR-14: 14 Position MDR Connector; Manufacturer: Generic Components; Package Information: Latest Revision: O; Positions: 15; Gender: Receptacle
U1 = XC2VP7-5FG456C: as U1 on sheet 9764-SLB Sandwich Adapter

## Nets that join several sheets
+2.5V: 9764-SLB Sandwich Adapter (J3.54 J3.56 J3.58 R13.1), 9764-SLB Sandwich Adapter Power (78 pins)
+3.3V: 9764-SLB Sandwich Adapter (26 pins), 9764-SLB Sandwich Adapter Power (14 pins)
GND: 9764-SLB Sandwich Adapter (133 pins), 9764-SLB Sandwich Adapter Power (131 pins), 9764-SLB Sandwich Adapter RocketIO (13 pins)
AVCCAUX1: 9764-SLB Sandwich Adapter Power (C7.1 L1.1), 9764-SLB Sandwich Adapter RocketIO (U1.B4)
AVCCAUX2: 9764-SLB Sandwich Adapter Power (C10.1 L4.1), 9764-SLB Sandwich Adapter RocketIO (U1.B6)
AVCCAUX3: 9764-SLB Sandwich Adapter Power (C13.1 L7.1), 9764-SLB Sandwich Adapter RocketIO (U1.B8)
AVCCAUX4: 9764-SLB Sandwich Adapter Power (C16.1 L10.1), 9764-SLB Sandwich Adapter RocketIO (U1.B10)
AVCCAUX5: 9764-SLB Sandwich Adapter Power (C19.1 L13.1), 9764-SLB Sandwich Adapter RocketIO (U1.B14)
AVCCAUX6: 9764-SLB Sandwich Adapter Power (C22.1 L16.1), 9764-SLB Sandwich Adapter RocketIO (U1.B16)
AVCCAUX7: 9764-SLB Sandwich Adapter Power (C25.1 L19.1), 9764-SLB Sandwich Adapter RocketIO (U1.B18)
AVCCAUX8: 9764-SLB Sandwich Adapter Power (C28.1 L22.1), 9764-SLB Sandwich Adapter RocketIO (U1.B20)
PROM_INIT_B: 9764-SLB Sandwich Adapter (U1.W17), 9764-SLB Sandwich Adapter Power (R20.1 U7.8)
RECB3: 9764-SLB Sandwich Adapter (J4.5 U1.V17), 9764-SLB Sandwich Adapter Power (U7.1)
TCK: 9764-SLB Sandwich Adapter (J3.50), 9764-SLB Sandwich Adapter Power (U1.B22 U7.6)
TDI: 9764-SLB Sandwich Adapter (J3.46), 9764-SLB Sandwich Adapter Power (U7.4)
TDO: 9764-SLB Sandwich Adapter (J3.52), 9764-SLB Sandwich Adapter Power (U1.D20)
TMS: 9764-SLB Sandwich Adapter (J3.48), 9764-SLB Sandwich Adapter Power (U1.A21 U7.5)
TX/~{RX}: 9764-SLB Sandwich Adapter (R13.2 U1.B11), 9764-SLB Sandwich Adapter RocketIO (J10.3)
VTRX1: 9764-SLB Sandwich Adapter Power (C9.1 L3.1), 9764-SLB Sandwich Adapter RocketIO (U1.B5)
VTRX2: 9764-SLB Sandwich Adapter Power (C12.1 L6.1), 9764-SLB Sandwich Adapter RocketIO (U1.B9)
VTRX3: 9764-SLB Sandwich Adapter Power (C15.1 L9.1), 9764-SLB Sandwich Adapter RocketIO (U1.B15)
VTRX4: 9764-SLB Sandwich Adapter Power (C18.1 L12.1), 9764-SLB Sandwich Adapter RocketIO (U1.B19)
VTTX1: 9764-SLB Sandwich Adapter Power (C8.1 L2.1), 9764-SLB Sandwich Adapter RocketIO (U1.B3)
VTTX2: 9764-SLB Sandwich Adapter Power (C11.1 L5.1), 9764-SLB Sandwich Adapter RocketIO (U1.B7)
VTTX3: 9764-SLB Sandwich Adapter Power (C14.1 L8.1), 9764-SLB Sandwich Adapter RocketIO (U1.B13)
VTTX4: 9764-SLB Sandwich Adapter Power (C17.1 L11.1), 9764-SLB Sandwich Adapter RocketIO (U1.B17)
